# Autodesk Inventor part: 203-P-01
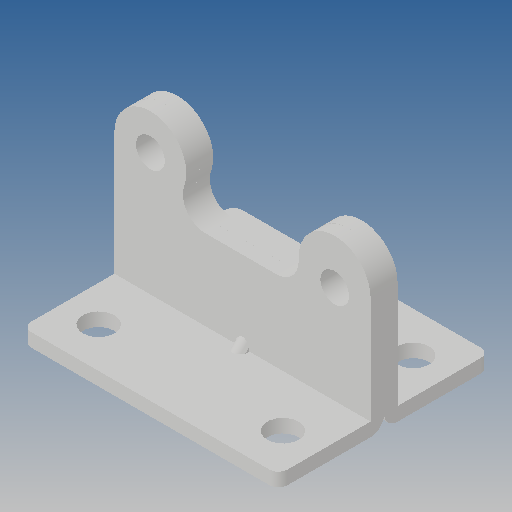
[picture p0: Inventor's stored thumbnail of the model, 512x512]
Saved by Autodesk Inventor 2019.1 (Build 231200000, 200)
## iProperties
Created: 2015-08
Part Number: 203-P-01
Material: Ogólny
Document SubType Name: Modeling
Designer: CADENGINEERING4
Density: 1 g/cm^3
Appearance: Domyślna
Author: CADENGINEERING4
Revision Number: ÈÎºÎ
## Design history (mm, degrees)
feature "NONE"
feature "NONE:1"
node "Bryła1"
node "Bryła2"
